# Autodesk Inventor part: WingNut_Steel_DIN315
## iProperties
Shininess: 64.0
Length Units: 11269
Angle Units: 11279
Time Units: 11290
Mass Units: 11283
Length Display Precision: 3
Angle Display Precision: 2
Compacted: True
Created: 2003-04
Part Number: WingNut_Steel_DIN315
Material: St.Galvanized
Document SubType Name: Modeling
Designer: Robbert Osinga
Description: Wingnut
Density: 0.0
Volumn: 0.0
Area: 0.0
PropertySet Name: Model Information
Control State: 0
Master: False
Checked Out: False
Author: Robbert Osinga
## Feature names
1. Extrusion2
2. Extrusion4
3. Revolution2
4. Fillet8
5. Fillet9
6. Fillet10
7. Extrusion7
